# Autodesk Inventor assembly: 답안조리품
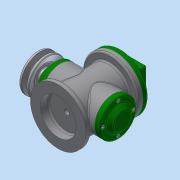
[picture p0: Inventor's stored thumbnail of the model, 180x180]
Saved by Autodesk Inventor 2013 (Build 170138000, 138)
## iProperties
Created: 2018-02
Part Number: 답안조리품
Document SubType Name: Assembly
Designer: dgall
Author: dgall
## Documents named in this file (18)
- C:\Users\dgall\Desktop\480207V1010\답안조리품.iam
- C:\Users\dgall\Desktop\480207V1010\본체.ipt
- C:\Users\dgall\Desktop\480207V1010\뒤커버.ipt
- C:\Users\dgall\Desktop\480207V1010\앞커버.ipt
- C:\Users\dgall\Desktop\480207V1010\오일 실 17 30 8.ipt
- C:\Users\dgall\Desktop\480207V1010\덮개.ipt
- C:\Users\dgall\Desktop\480207V1010\베어링 17 x 40 x 12.ipt
- C:\Users\dgall\Desktop\480207V1010\편심축.ipt
- C:\Users\dgall\Desktop\480207V1010\키 4 x 4 x 12.ipt
- C:\Users\dgall\Desktop\480207V1010\V-벨트풀리.ipt
- C:\Users\dgall\Desktop\480207V1010\볼트 M4 x 10.ipt
- C:\Users\dgall\Desktop\480207V1010\와셔 4x16.ipt
- C:\Users\dgall\Desktop\480207V1010\슬라이더.ipt
- C:\Users\dgall\Desktop\480207V1010\링크.ipt
- C:\Users\dgall\Desktop\480207V1010\클레비스 핀 6 x 22.ipt
- 클레비스 핀 6 x 22.ipt
- C:\Users\dgall\Desktop\480207V1010\E-링.ipt
- C:\Users\dgall\Desktop\480207V1010\볼트 M4 x 8.ipt
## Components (2 placed, 2 different names)
1. V-벨트풀리:1
2. E-링:1
